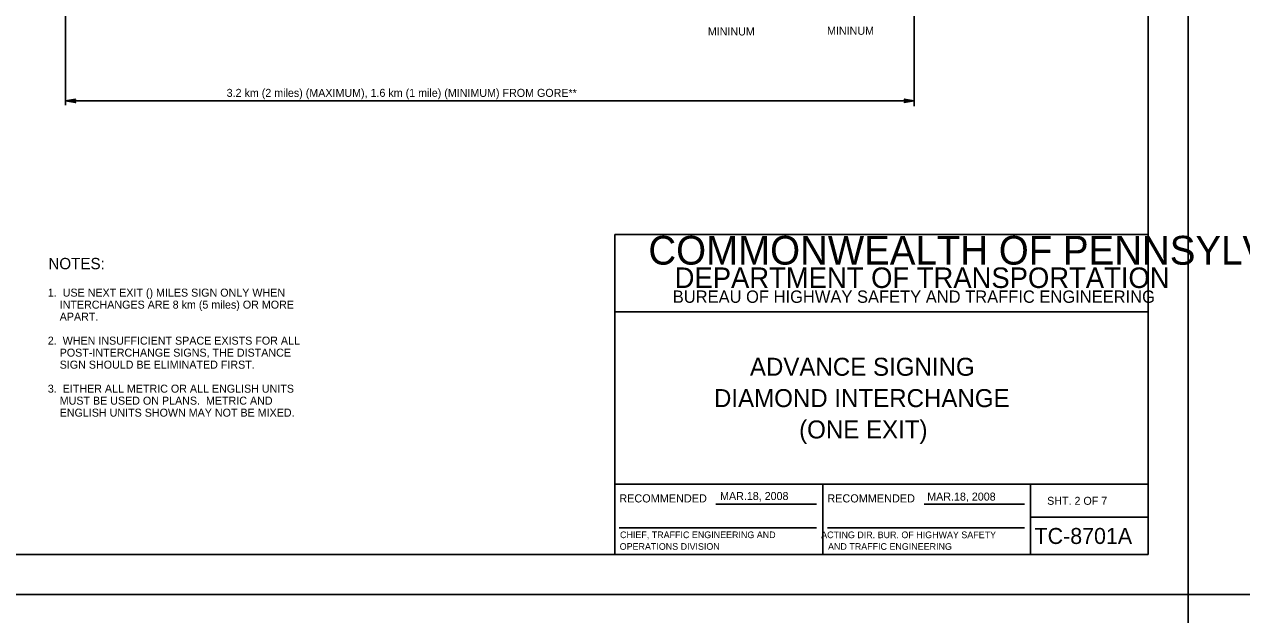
# Model space of a CAD drawing. Extents: x 640994 to 644422, y 298458 to 299646.
# Drawn here: x 642240 to 642696.3, y 299044.1 to 299265.4 of the extents above; entities that cross this region are included whole.
import ezdxf

# ---------------------------------------------------------------- set-up
doc = ezdxf.new("R2010")
doc.units = 0
for name, color, linetype in [('1', 7, 'Continuous'), ('2', 7, 'Continuous'), ('PLT-BNDY', 7, 'Continuous'), ('XCS-GRID-MIN', 7, 'Continuous')]:
    doc.layers.add(name, color=color, linetype=linetype)

msp = doc.modelspace()

# ---------------------------------------------------------------- linework, layer by layer
at = {"layer": '1'}
for p, q in [((642661.31, 299066.63), (642661.31, 299630.63)), ((642461.31, 299066.63), (642461.31, 299186.63)), ((642461.31, 299186.63), (642661.31, 299186.63)), ((642661.31, 299157.63), (642461.31, 299157.63)), ((642461.31, 299093), (642661.31, 299093)), ((642539.31, 299093), (642539.31, 299066.63)), ((642617.19, 299066.63), (642617.19, 299093)), ((642499.24, 299085.57), (642536.87, 299085.57)), ((642577.24, 299085.57), (642614.87, 299085.57)), ((642617.19, 299080.63), (642661.31, 299080.63)), ((642462.99, 299076.68), (642536.87, 299076.68)), ((642540.99, 299076.68), (642614.87, 299076.68)), ((642661.31, 299066.63), (641875.31, 299066.63)), ((641875.31, 299066.63), (642461.31, 299066.63))]:
    msp.add_line(p, q, dxfattribs=at)
at = {"layer": '2'}
for p, q in [((642573.56, 299352.88), (642573.56, 299234.75)), ((642255.44, 299338.75), (642255.44, 299235.13)), ((642573.56, 299236.75), (642255.44, 299236.75))]:
    msp.add_line(p, q, dxfattribs=at)
for points in [[(642258.94, 299236.25), (642258.81, 299236.5), (642255.44, 299236.75), (642258.94, 299236.25), (642259.19, 299236.13), (642255.44, 299236.75), (642258.81, 299236.88), (642258.94, 299237.13), (642255.44, 299236.75), (642259.19, 299237.38), (642258.94, 299237.13)], [(642570.06, 299237.25), (642570.19, 299237), (642573.56, 299236.75), (642570.06, 299237.25), (642569.81, 299237.38), (642573.56, 299236.75), (642570.19, 299236.63), (642570.06, 299236.38), (642573.56, 299236.75), (642569.81, 299236.13), (642570.06, 299236.38)]]:
    msp.add_lwpolyline(points, dxfattribs=at)
at = {"layer": 'XCS-GRID-MIN'}
for points in [[(641835.31, 299645.63), (642676.31, 299645.63), (642676.31, 299051.63), (641835.31, 299051.63)], [(642676.31, 299645.63), (643517.31, 299645.63), (643517.31, 299051.63), (642676.31, 299051.63)], [(641835.31, 299051.63), (642676.31, 299051.63), (642676.31, 298457.63), (641835.31, 298457.63)], [(642676.31, 299051.63), (643517.31, 299051.63), (643517.31, 298457.63), (642676.31, 298457.63)]]:
    msp.add_lwpolyline(points, close=True, dxfattribs=at)

# ---------------------------------------------------------------- texts
at = {"layer": '1'}
for s, height, p in [('COMMONWEALTH OF PENNSYLVANIA', 10.7828, (642473.9, 299175.36)), ('DEPARTMENT OF TRANSPORTATION', 7.6837, (642483.76, 299166.61)), ('BUREAU OF HIGHWAY SAFETY AND TRAFFIC ENGINEERING', 4.6253, (642483.04, 299161.04)), ('ADVANCE SIGNING', 6.75, (642511.96, 299133.69)), ('DIAMOND INTERCHANGE', 6.75, (642498.49, 299121.94)), ('(ONE EXIT)', 6.75, (642530.41, 299110.19)), ('RECOMMENDED', 3.048, (642462.99, 299086.2)), ('RECOMMENDED', 3.048, (642540.99, 299086.2)), ('SHT. 2 OF 7', 3, (642623.4, 299085.31)), ('TC-8701A', 6, (642618.68, 299070.63))]:
    msp.add_text(s, height=height, dxfattribs=at).set_placement(p)
at = {"layer": '2'}
for s, height, p in [(' MININUM', 3, (642495.07, 299261.28)), (' MININUM', 3, (642539.76, 299261.54)), ('3.2 km (2 miles) (MAXIMUM), 1.6 km (1 mile) (MINIMUM) FROM GORE**', 3, (642315.8, 299238.25)), ('NOTES:', 4.25, (642248.97, 299173.63)), ('1.  USE NEXT EXIT () MILES SIGN ONLY WHEN', 3, (642248.75, 299163.36)), ('    INTERCHANGES ARE 8 km (5 miles) OR MORE', 3, (642248.75, 299158.86)), ('    APART.', 3, (642248.75, 299154.36)), ('2.  WHEN INSUFFICIENT SPACE EXISTS FOR ALL', 3, (642248.75, 299145.36)), ('    POST-INTERCHANGE SIGNS, THE DISTANCE', 3, (642248.75, 299140.86)), ('    SIGN SHOULD BE ELIMINATED FIRST.', 3, (642248.75, 299136.36)), ('3.  EITHER ALL METRIC OR ALL ENGLISH UNITS', 3, (642248.75, 299127.36)), ('    MUST BE USED ON PLANS.  METRIC AND', 3, (642248.75, 299122.86)), ('    ENGLISH UNITS SHOWN MAY NOT BE MIXED.', 3, (642248.75, 299118.36)), ('MAR.18, 2008', 3, (642500.78, 299087.1)), ('MAR.18, 2008', 3, (642578.44, 299086.89))]:
    msp.add_text(s, height=height, dxfattribs=at).set_placement(p)
at = {"layer": 'PLT-BNDY'}
for s, p in [('CHIEF, TRAFFIC ENGINEERING AND', (642463.28, 299072.81)), ('  ACTING DIR. BUR. OF HIGHWAY SAFETY', (642536.81, 299072.8)), ('  ACTING DIR. BUR. OF HIGHWAY SAFETY', (642536.81, 299072.8)), ('OPERATIONS DIVISION', (642463.14, 299068.44))]:
    msp.add_text(s, height=2.5, dxfattribs=at).set_placement(p)
msp.add_text('AND TRAFFIC ENGINEERING', height=2.5, rotation=360, dxfattribs=at).set_placement((642541.25, 299068.43))
msp.add_text('AND TRAFFIC ENGINEERING', height=2.5, rotation=360, dxfattribs=at).set_placement((642541.25, 299068.43))

doc.saveas('drawing.dxf')
